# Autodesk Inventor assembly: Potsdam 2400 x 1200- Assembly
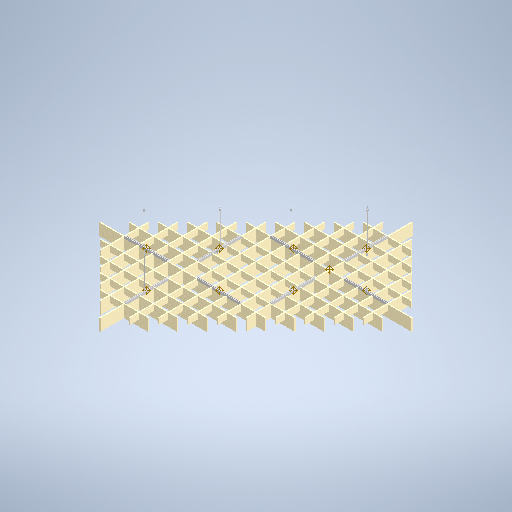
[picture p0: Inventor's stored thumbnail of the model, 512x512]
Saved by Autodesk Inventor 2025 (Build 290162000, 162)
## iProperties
Created: 2024-06
Part Number: Potsdam 2400 x 1200- Assembly
Document SubType Name: Assembly
Designer: Dom Harlow
Author: Dom Harlow
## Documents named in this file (15)
- C:\Users\GeorgeBrown\Synergy commercial Lighting\Synergy Shared - Public\Synergy\Synergy Drawings\S0079 - Potsdam Acoustic Baffle\Design\General Assemblies\Potsdam 2400 x 1200\Potsdam 2400 x 1200- Assembly.iam
- C:\Users\GeorgeBrown\Synergy commercial Lighting\Synergy Shared - Public\Synergy\Synergy Drawings\S0079 - Potsdam Acoustic Baffle\Design\Parts\S0079_1200x2400\Inventor\Parts\Potsdam - Part K.ipt
- C:\Users\GeorgeBrown\Synergy commercial Lighting\Synergy Shared - Public\Synergy\Synergy Drawings\S0079 - Potsdam Acoustic Baffle\Design\Parts\S0079_1200x2400\Inventor\Parts\Potsdam - Part M.ipt
- C:\Users\GeorgeBrown\Synergy commercial Lighting\Synergy Shared - Public\Synergy\Synergy Drawings\S0079 - Potsdam Acoustic Baffle\Design\Parts\S0079_1200x2400\Inventor\Parts\Potsdam - Part E.ipt
- C:\Users\GeorgeBrown\Synergy commercial Lighting\Synergy Shared - Public\Synergy\Synergy Drawings\S0079 - Potsdam Acoustic Baffle\Design\Parts\S0079_1200x2400\Inventor\Parts\Potsdam - Part F.ipt
- C:\Users\GeorgeBrown\Synergy commercial Lighting\Synergy Shared - Public\Synergy\Synergy Drawings\S0079 - Potsdam Acoustic Baffle\Design\Parts\S0079_1200x2400\Inventor\Parts\Potsdam - Part J.ipt
- C:\Users\GeorgeBrown\Synergy commercial Lighting\Synergy Shared - Public\Synergy\Synergy Drawings\S0079 - Potsdam Acoustic Baffle\Design\Parts\S0079_1200x2400\Inventor\Parts\Potsdam - Part L.ipt
- C:\Users\GeorgeBrown\Synergy commercial Lighting\Synergy Shared - Public\Synergy\Synergy Drawings\S0079 - Potsdam Acoustic Baffle\Design\Parts\S0079_1200x2400\Inventor\Parts\Potsdam - Part G.ipt
- C:\Users\GeorgeBrown\Synergy commercial Lighting\Synergy Shared - Public\Synergy\Synergy Drawings\S0079 - Potsdam Acoustic Baffle\Design\Parts\S0079_1200x2400\Inventor\Parts\Potsdam - Part H.ipt
- C:\Users\GeorgeBrown\Synergy commercial Lighting\Synergy Shared - Public\Synergy\Synergy Drawings\S0079 - Potsdam Acoustic Baffle\Design\Parts\S0079_1200x2400\Inventor\Parts\Potsdam - Part A.ipt
- C:\Users\GeorgeBrown\Synergy commercial Lighting\Synergy Shared - Public\Synergy\Synergy Drawings\S0079 - Potsdam Acoustic Baffle\Design\Parts\S0079_1200x2400\Inventor\Parts\Potsdam - Part B.ipt
- C:\Users\GeorgeBrown\Synergy commercial Lighting\Synergy Shared - Public\Synergy\Synergy Drawings\S0079 - Potsdam Acoustic Baffle\Design\Parts\S0079_1200x2400\Inventor\Parts\Potsdam - Part C.ipt
- C:\Users\GeorgeBrown\Synergy commercial Lighting\Synergy Shared - Public\Synergy\Synergy Drawings\S0079 - Potsdam Acoustic Baffle\Design\Parts\S0079_1200x2400\Inventor\Parts\Potsdam - Part D.ipt
- C:\Users\GeorgeBrown\Synergy commercial Lighting\Synergy Shared - Public\Synergy\Synergy Drawings\F-Code Components\F000264 - 2m suspension kit\F000264 - Wire suspension.iam
- C:\Users\GeorgeBrown\Synergy commercial Lighting\Synergy Shared - Public\Synergy\Synergy Drawings\Acoustic ACF parts\12mm Sus rail 0438.ipt
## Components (45 placed, 14 different names)
1. Potsdam - Part F:1
2. Potsdam - Part E:1
3. Potsdam - Part G:1
4. Potsdam - Part H:1
5. Potsdam - Part A:1 — Mate:13, Mate:14, Mate:15
6. Potsdam - Part B:1 — Mate:22, Mate:23, Mate:24
7. Potsdam - Part C:1 — Mate:34, Mate:35, Mate:36
8. Potsdam - Part D:1 — Mate:55, Mate:56, Mate:57
9. Potsdam - Part A:2 — Mate:19, Mate:20, Mate:21, Mate:80, Mate:81, Mate:84
10. Potsdam - Part B:2 — Mate:25, Mate:26, Mate:27
11. Potsdam - Part D:2 — Mate:46, Mate:47, Mate:48
12. Potsdam - Part C:2 — Mate:40, Mate:41, Mate:42
13. Potsdam - Part A:3 — Mate:10, Mate:11, Mate:12
14. Potsdam - Part B:3 — Mate:28, Mate:29, Mate:30
15. Potsdam - Part C:3 — Mate:43, Mate:44, Mate:45
16. Potsdam - Part D:3 — Mate:49, Mate:50, Mate:51
17. Potsdam - Part A:4 — Mate:16, Mate:17, Mate:18
18. Potsdam - Part B:4 — Mate:31, Mate:32, Mate:33
19. Potsdam - Part C:4 — Mate:37, Mate:38, Mate:39
20. Potsdam - Part D:4 — Mate:52, Mate:53, Mate:54
21. Potsdam - Part L:1 — Mate:58, Mate:59, Mate:60
22. Potsdam - Part K:1 — Mate:67, Mate:68, Mate:69
23. Potsdam - Part J:1 — Mate:64, Mate:65, Mate:66
24. Potsdam - Part M:1 — Mate:61, Mate:62, Mate:63, Mate:71
25. Potsdam - Part L:2 — Mate:92, Mate:93, Mate:94
26. Potsdam - Part M:3 — Mate:79, Mate:80, Mate:81
27. Potsdam - Part K:2 — Mate:70, Mate:71, Mate:72
28. Potsdam - Part J:2 — Mate:73, Mate:74, Mate:75
29. 12mm Sus rail 0438:8 — Mate:91
30. F000264 - Wire suspension:12 [sub-assembly] — Mate:91
31. 12mm Sus rail 0438:9
32. F000264 - Wire suspension:13 [sub-assembly]
33. 12mm Sus rail 0438:10
34. F000264 - Wire suspension:14 [sub-assembly]
35. 12mm Sus rail 0438:11
36. F000264 - Wire suspension:15 [sub-assembly]
37. F000264 - Wire suspension:16 [sub-assembly]
38. 12mm Sus rail 0438:4 — Mate:82, Mate:83, Mate:84, Mate:85
39. F000264 - Wire suspension:4 [sub-assembly] — Mate:85
40. 12mm Sus rail 0438:5
41. F000264 - Wire suspension:9 [sub-assembly]
42. 12mm Sus rail 0438:6
43. F000264 - Wire suspension:10 [sub-assembly]
44. 12mm Sus rail 0438:7
45. F000264 - Wire suspension:11 [sub-assembly]
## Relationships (77: Mate 77)
- Mate:10: Potsdam - Part A:3
- Mate:11: Potsdam - Part A:3
- Mate:12: Potsdam - Part A:3
- Mate:13: Potsdam - Part A:1
- Mate:14: Potsdam - Part A:1
- Mate:15: Potsdam - Part A:1
- Mate:16: Potsdam - Part A:4
- Mate:17: Potsdam - Part A:4
- Mate:18: Potsdam - Part A:4
- Mate:19: Potsdam - Part A:2
- Mate:20: Potsdam - Part A:2
- Mate:21: Potsdam - Part A:2
- Mate:22: Potsdam - Part B:1
- Mate:23: Potsdam - Part B:1
- Mate:24: Potsdam - Part B:1
- Mate:25: Potsdam - Part B:2
- Mate:26: Potsdam - Part B:2
- Mate:27: Potsdam - Part B:2
- Mate:28: Potsdam - Part B:3
- Mate:29: Potsdam - Part B:3
- Mate:30: Potsdam - Part B:3
- Mate:31: Potsdam - Part B:4
- Mate:32: Potsdam - Part B:4
- Mate:33: Potsdam - Part B:4
- Mate:34: Potsdam - Part C:1
- Mate:35: Potsdam - Part C:1
- Mate:36: Potsdam - Part C:1
- Mate:37: Potsdam - Part C:4
- Mate:38: Potsdam - Part C:4
- Mate:39: Potsdam - Part C:4
- Mate:40: Potsdam - Part C:2
- Mate:41: Potsdam - Part C:2
- Mate:42: Potsdam - Part C:2
- Mate:43: Potsdam - Part C:3
- Mate:44: Potsdam - Part C:3
- Mate:45: Potsdam - Part C:3
- Mate:46: Potsdam - Part D:2
- Mate:47: Potsdam - Part D:2
- Mate:48: Potsdam - Part D:2
- Mate:49: Potsdam - Part D:3
- Mate:50: Potsdam - Part D:3
- Mate:51: Potsdam - Part D:3
- Mate:52: Potsdam - Part D:4
- Mate:53: Potsdam - Part D:4
- Mate:54: Potsdam - Part D:4
- Mate:55: Potsdam - Part D:1
- Mate:56: Potsdam - Part D:1
- Mate:57: Potsdam - Part D:1
- Mate:58: Potsdam - Part L:1
- Mate:59: Potsdam - Part L:1
- Mate:60: Potsdam - Part L:1
- Mate:61: Potsdam - Part M:1
- Mate:62: Potsdam - Part M:1
- Mate:63: Potsdam - Part M:1
- Mate:64: Potsdam - Part J:1
- Mate:65: Potsdam - Part J:1
- Mate:66: Potsdam - Part J:1
- Mate:67: Potsdam - Part K:1
- Mate:68: Potsdam - Part K:1
- Mate:69: Potsdam - Part K:1
- Mate:70: Potsdam - Part K:2
- Mate:71: Potsdam - Part M:1 ↔ Potsdam - Part K:2
- Mate:72: Potsdam - Part K:2
- Mate:73: Potsdam - Part J:2
- Mate:74: Potsdam - Part J:2
- Mate:75: Potsdam - Part J:2
- Mate:79: Potsdam - Part M:3
- Mate:80: Potsdam - Part A:2 ↔ Potsdam - Part M:3
- Mate:81: Potsdam - Part A:2 ↔ Potsdam - Part M:3
- Mate:82: 12mm Sus rail 0438:4
- Mate:83: 12mm Sus rail 0438:4
- Mate:84: Potsdam - Part A:2 ↔ 12mm Sus rail 0438:4
- Mate:85: 12mm Sus rail 0438:4 ↔ F000264 - Wire suspension:4
- Mate:91: 12mm Sus rail 0438:8 ↔ F000264 - Wire suspension:12
- Mate:92: Potsdam - Part L:2
- Mate:93: Potsdam - Part L:2
- Mate:94: Potsdam - Part L:2
